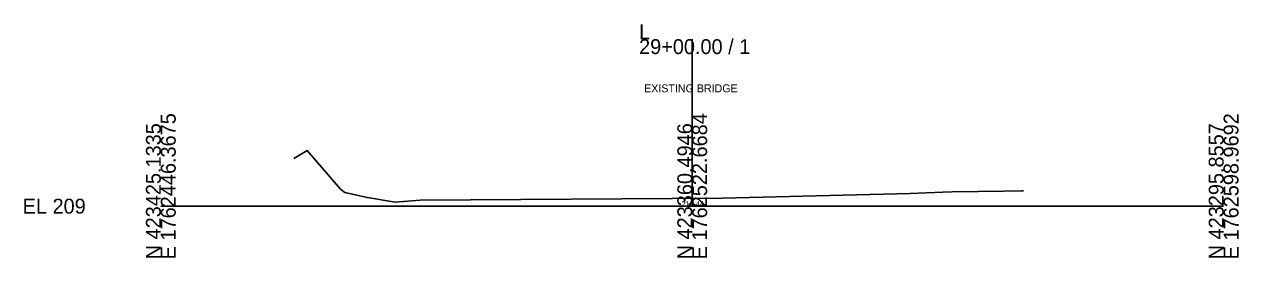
# Model space of a CAD drawing. Extents: x -26 to 3203, y -11010 to 4024.
# Drawn here: x -25.7 to 202.8, y 3490.3 to 3534.2 of the extents above; entities that cross this region are included whole.
import ezdxf

# ---------------------------------------------------------------- set-up
doc = ezdxf.new("R2010")
doc.units = 0
for name, color, linetype in [('Default', 7, 'Continuous'), ('Exist Cross Section Cell', 7, 'Continuous'), ('Exist XS Center Line Elevation Label', 7, 'Continuous'), ('Exist XS Ground Line', 7, 'Continuous'), ('Prop XS SE Text', 7, 'Continuous')]:
    doc.layers.add(name, color=color, linetype=linetype)

msp = doc.modelspace()

# ---------------------------------------------------------------- linework, layer by layer
at = {"layer": 'Exist Cross Section Cell'}
for p, q in [((100, 3500), (100, 3531.41)), ((0, 3500), (100, 3500)), ((100, 3500), (200, 3500))]:
    msp.add_line(p, q, dxfattribs=at)
at = {"layer": 'Exist XS Ground Line'}
msp.add_lwpolyline([(25.02, 3508.97), (27.51, 3510.47), (33.83, 3503.22), (34.6, 3502.58), (38.88, 3501.61), (44.08, 3500.75), (48.79, 3501.15), (105.71, 3501.48), (141.03, 3502.36), (147.18, 3502.64), (148.93, 3502.7), (158.63, 3502.84), (162.03, 3502.89), (162.31, 3502.89)], dxfattribs=at)
msp.add_lwpolyline([(25.02, 3508.97), (27.51, 3510.47), (33.83, 3503.22), (34.6, 3502.58), (38.88, 3501.61), (44.08, 3500.75), (48.79, 3501.15), (105.71, 3501.48), (141.03, 3502.36), (147.18, 3502.64), (148.93, 3502.7), (158.63, 3502.84), (162.03, 3502.89), (162.31, 3502.89)], dxfattribs=at)
msp.add_lwpolyline([(25.02, 3508.97), (27.51, 3510.47), (33.83, 3503.22), (34.6, 3502.58), (38.88, 3501.61), (44.08, 3500.75), (48.79, 3501.15), (105.71, 3501.48), (141.03, 3502.36), (147.18, 3502.64), (148.93, 3502.7), (158.63, 3502.84), (162.03, 3502.89), (162.31, 3502.89)], dxfattribs=at)
msp.add_lwpolyline([(25.02, 3508.97), (27.51, 3510.47), (33.83, 3503.22), (34.6, 3502.58), (38.88, 3501.61), (44.08, 3500.75), (48.79, 3501.15), (105.71, 3501.48), (141.03, 3502.36), (147.18, 3502.64), (148.93, 3502.7), (158.63, 3502.84), (162.03, 3502.89), (162.31, 3502.89)], dxfattribs=at)
msp.add_lwpolyline([(25.02, 3508.97), (27.51, 3510.47), (33.83, 3503.22), (34.6, 3502.58), (38.88, 3501.61), (44.08, 3500.75), (48.79, 3501.15), (105.71, 3501.48), (141.03, 3502.36), (147.18, 3502.64), (148.93, 3502.7), (158.63, 3502.84), (162.03, 3502.89), (162.31, 3502.89)], dxfattribs=at)

# ---------------------------------------------------------------- texts
at = {"layer": 'Default'}
msp.add_text('-', height=0.0001, dxfattribs=at).set_placement((0, 3500))
at = {"layer": 'Exist Cross Section Cell'}
for s, p in [('L', (90, 3531.41)), ('29+00.00 / 1', (90, 3528.61)), ('EL 209', (-26, 3498.6))]:
    msp.add_text(s, height=2.8, dxfattribs=at).set_placement(p)
for s, p in [('E 1762446.3675', (2.8, 3490)), ('E 1762522.6684', (102.8, 3490)), ('E 1762598.9692', (202.8, 3490)), ('N 423425.1335', (0, 3490)), ('N 423360.4946', (100, 3490)), ('N 423295.8557', (200, 3490))]:
    msp.add_text(s, height=2.8, rotation=90, dxfattribs=at).set_placement(p)
at = {"layer": 'Exist XS Center Line Elevation Label'}
msp.add_text('210.44', height=1, dxfattribs=at).set_placement((97.98, 3499.94))
at = {"layer": 'Prop XS SE Text'}
msp.add_text('EXISTING BRIDGE', height=1.5, rotation=360, dxfattribs=at).set_placement((90.95, 3521.41))

doc.saveas('drawing.dxf')
